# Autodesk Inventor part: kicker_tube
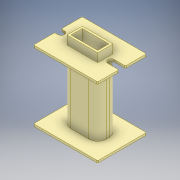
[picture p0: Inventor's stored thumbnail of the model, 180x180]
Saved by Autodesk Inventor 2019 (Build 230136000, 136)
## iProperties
Created: 2019-01
Part Number: kicker_tube
Material: Nylon 6/6
Document SubType Name: Modeling
Designer: steve
Density: 1.13 g/cm^3
Appearance: Nylon 6
Created: 2019-05
Part Number: kicker_tube_3DPrint
Material: Générique
Density: 1 g/cm^3
Appearance: Par défaut
Author: steve
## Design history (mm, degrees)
sketch "Sketch1"
  geometry: L1 (-6.075, -2.575)-(6.075, -2.575); L2 (6.075, -2.575)-(6.075, 2.575); L3 (6.075, 2.575)-(-6.075, 2.575); L4 (-6.075, 2.575)-(-6.075, -2.575); L5 (-6.075, -2.575)-(6.075, 2.575); L6 (6.075, -2.575)-(-6.075, 2.575); L7 (-8.075, 4.575)-(8.075, 4.575); L8 (8.075, 4.575)-(8.075, -4.575); L9 (8.075, -4.575)-(-8.075, -4.575); L10 (-8.075, -4.575)-(-8.075, 4.575); 1 further point
  constraints: 20 end point, 4 parallel, 2 midpoint, 2 perpendicular, 1 horizontal, 3 other
  dimensions: "d0" = 5.15 distance between parallel lines of L1 L3; "d1" = 12.15 distance between parallel lines of L2 L4; "d2" = 2 distance between parallel lines of L3 L7 (= ep)
extrude "Extrusion1" new body sketch "Sketch1" distance "d3" = 30; taper "d4" = 0 deg
sketch "Sketch2"
  geometry: L1 (14.575, -11.075)-(-14.575, -11.075); L2 (-14.575, -11.075)-(-14.575, 11.075); L3 (-14.575, 11.075)-(14.575, 11.075); L4 (14.575, 11.075)-(14.575, -11.075); L5 (14.575, -11.075)-(-14.575, 11.075); L6 (-14.575, -11.075)-(14.575, 11.075); L7 (8.075, 4.575)-(-8.075, 4.575) reference; L8 (-8.075, 4.575)-(-8.075, -4.575) reference; L9 (8.075, -4.575)-(8.075, 4.575) reference; L10 (-6.075, -2.575)-(-6.075, 2.575) reference; L11 (-6.075, 2.575)-(6.075, 2.575) reference; L12 (6.075, 2.575)-(6.075, -2.575) reference; L13 (6.075, -2.575)-(-6.075, -2.575) reference; L14 (8.075, 4.575)-(-8.075, 4.575) reference; L15 (-8.075, 4.575)-(-8.075, -4.575) reference; L16 (-8.075, -4.575)-(8.075, -4.575) reference; L17 (8.075, -4.575)-(8.075, 4.575) reference; 1 further point
  constraints: 12 end point, 2 midpoint, 2 parallel, 1 horizontal, 1 perpendicular
  dimensions: "d5" = 6.5 distance between parallel lines of L3 L7; "d6" = 6.5 distance between parallel lines of L8 L2
extrude "Extrusion2" join sketch "Sketch2" distance "d7" = 1; taper "d8" = 0 deg
workplane "Work Plane1"
mirror "Mirror1"
fillet "Fillet1" dims "d9" = 4
sketch "Sketch3"
  geometry: L1 (6.075, 2.575)-(6.075, -2.575) reference; L2 (-6.075, 2.575)-(6.075, 2.575) reference; L3 (-6.075, -2.575)-(-6.075, 2.575) reference; L4 (6.075, -2.575)-(-6.075, -2.575) reference; L5 (-6.975, -3.475)-(-6.975, 3.475); L6 (-6.975, 3.475)-(6.975, 3.475); L7 (6.975, 3.475)-(6.975, -3.475); L8 (6.975, -3.475)-(-6.975, -3.475); 1 further point
  constraints: 8 end point, 3 other
  dimensions: "d10" = 0.9 distance between parallel lines of L4 L8
extrude "Extrusion3" join sketch "Sketch3" distance "d11" = 3.9; taper "d12" = 0 deg
mirror "Mirror2"
sketch "Sketch5"
  geometry: L1 (-8.075, -0.575)-(-8.075, 0.575) reference; L2 (-20.405, 0)-(20.405, 0) reference; L3 (-8.075, -1.5)-(-14.575, -1.5); L4 (-14.575, -1.5)-(-14.575, 1.5); L5 (-14.575, 1.5)-(-8.075, 1.5); L6 (-8.075, 1.5)-(-8.075, -1.5); L7 (-8.075, -1.5)-(-14.575, 1.5); L8 (-14.575, -1.5)-(-8.075, 1.5); L9 (-14.575, -11.075)-(-14.575, 11.075) reference; L10 (-9.575, 1.5)-(-14.575, 1.5); L11 (-14.575, 1.5)-(-14.575, -1.5); L12 (-14.575, -1.5)-(-9.575, -1.5); L13 (-9.575, 0)-(-9.575, 1.965); L14 (11.575, 3.029)-(11.575, -4.419); L15 (14.575, 11.075)-(14.575, -11.075) reference; L16 (14.575, -1.5)-(11.575, -1.5); L17 (11.575, -1.5)-(11.575, 1.5); L18 (11.575, 1.5)-(14.575, 1.5); L19 (14.575, 1.5)-(14.575, -1.5); L20 (14.575, -1.5)-(11.575, 1.5); L21 (11.575, -1.5)-(14.575, 1.5); L22 (13.075, 1.5)-(14.575, 1.5); L23 (14.575, 1.5)-(14.575, -1.5); L24 (14.575, -1.5)-(13.075, -1.5); A1 r 1.5 centre (-9.575, 0) between (-9.575, -1.5) and (-9.575, 1.5); A2 r 1.5 centre (13.075, 0) between (13.075, 1.5) and (13.075, -1.5); 4 further points
  constraints: 40 end point, 7 collinear, 7 point on line, 6 midpoint, 4 parallel, 4 point on circle, 3 perpendicular, 2 centre point, 2 coincident, 2 horizontal, 2 vertical
  dimensions: "d13" = 3 distance between parallel lines of L3 L5; "d14" = 1.5 distance from line of L6 point (-9.575, 0); "d15" = 3 distance between parallel lines of L14 L15; "d16" = 1.5 distance from line of L14 point (13.075, 0); "d17" = 3 distance between parallel lines of L16 L18
extrude "Extrusion4" cut sketch "Sketch5" extent not by distance; stored distance "d18" = 10; taper "d19" = 0 deg
fillet "Fillet2" dims "d20" = 0.5
body "Solid1"
node "Projected Loop1"
other parameters: "ep" = 2 [user parameter; used in 1 equation term]
